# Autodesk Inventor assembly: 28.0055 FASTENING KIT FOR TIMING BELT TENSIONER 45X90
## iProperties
Created: 2007-06
Part Number: 28.0055 FASTENING KIT FOR TIMING BELT TENSIONER 45X90
Document SubType Name: Assembly
Designer: Andy Moles
Author: Andy Moles
